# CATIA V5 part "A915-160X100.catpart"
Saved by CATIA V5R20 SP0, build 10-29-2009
Part number: A915-160X100
Source: Unknown
Property "A": "110.000"
Property "ARTICLENO": "A915-160X100"
Property "BOMINFO": "A915-160X100"
Property "CODE": "A915-160X100"
Property "CREATOR": "CADENAS GmbH"
Property "D": "13.500"
Property "D1": "20.000"
Property "FORM": "C"
Property "L": "100.000"
Property "L1": "25.000"
Property "L2": "50.000"
Property "LINA": "A915-160X100"
Property "NB": "A915-160X100"
Property "NBSYN": "$CODE."
Property "NN": "A915"
Property "NT": "VDI 3357 Wear Plates, steel"
Property "SCREW": "M12x25"
Property "SUPPLIER": "CF"
Property "T": "13.000"
Property "W": "160.000"
Bounding box of the stored display mesh (mm): x 0 to 20, y 0 to 100, z -80 to 80
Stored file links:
  C:\Users\borellobunino\Desktop\3D X SITO CF\A915\GSB_OILLESS_G22501160100\CATIAV5\A915-160X100.catpart
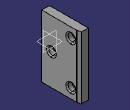
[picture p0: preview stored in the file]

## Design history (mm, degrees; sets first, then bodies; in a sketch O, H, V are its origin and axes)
Body1 "Geometry.1" (main body)
  Solid1 "A915-160X100.catpart": solid without history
